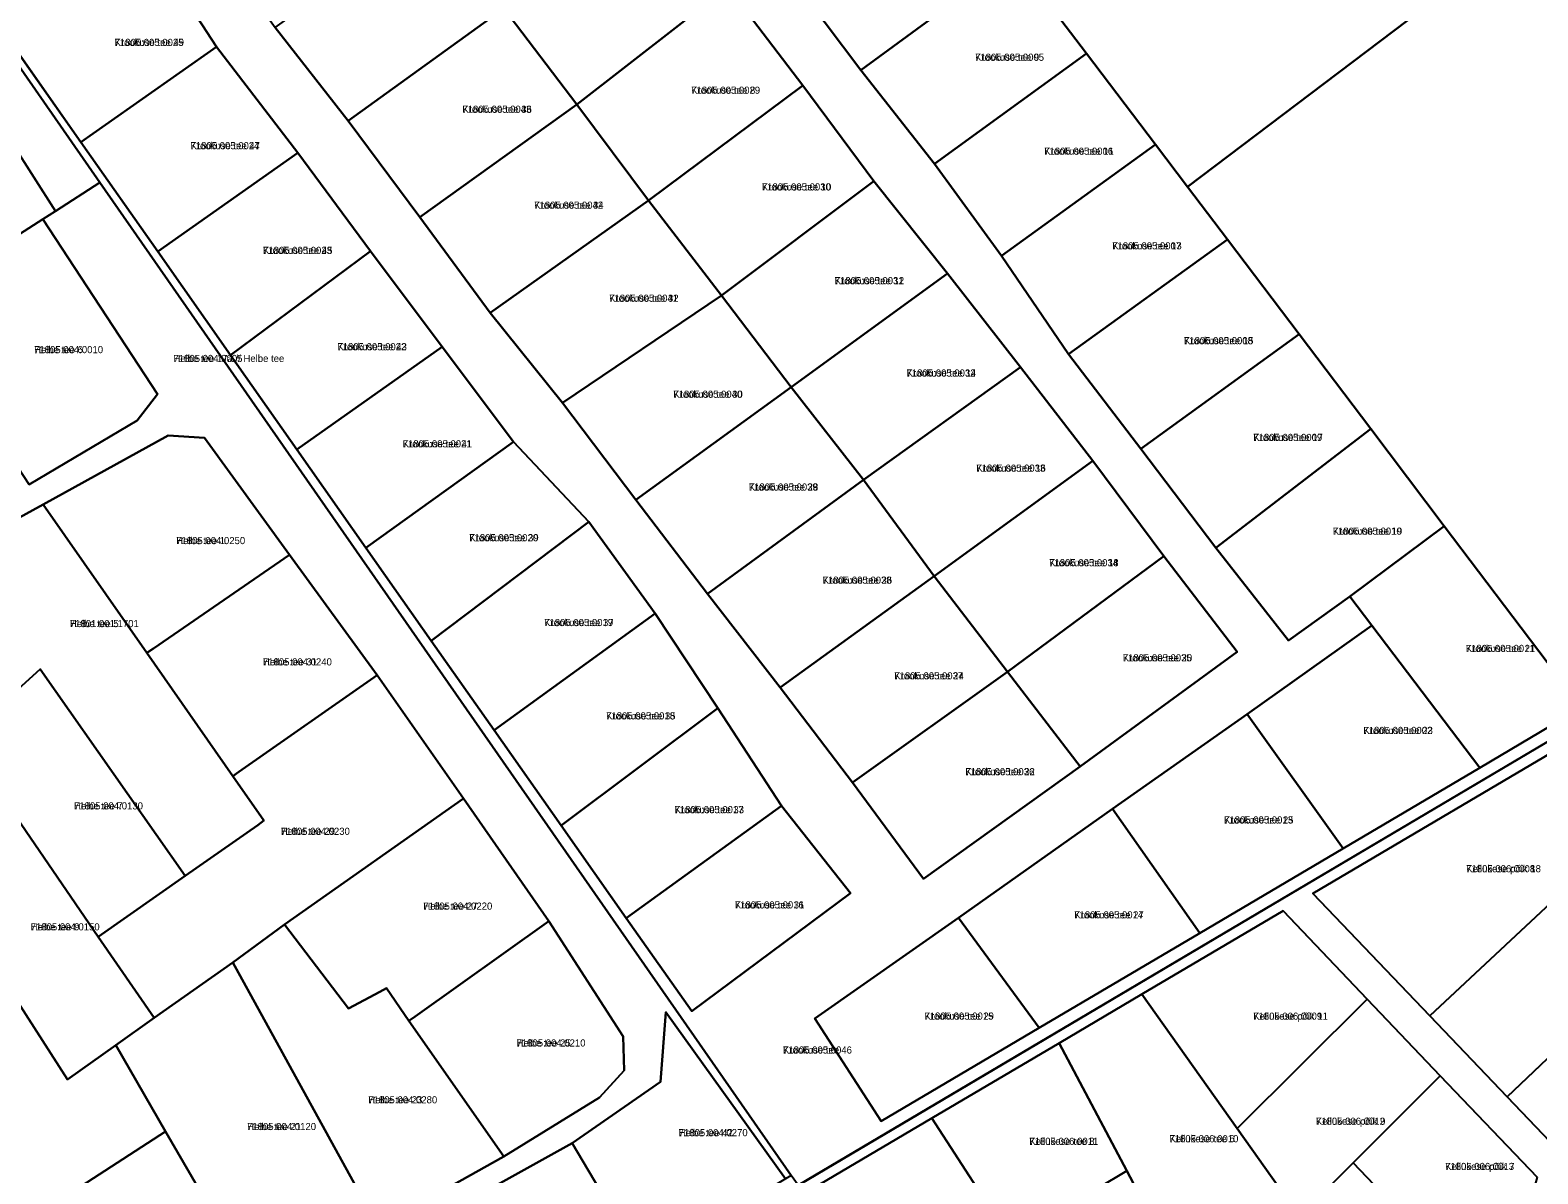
# Model space of a CAD drawing. Extents: x 529768 to 552006, y 6562269 to 6580975.
# Drawn here: x 537375.5 to 537692.6, y 6571376.5 to 6571616.9 of the extents above; entities that cross this region are included whole.
import ezdxf

# ---------------------------------------------------------------- set-up
doc = ezdxf.new("R2010")
doc.units = 0
for name, color, linetype in [('L_AADRESS', 7, 'Continuous'), ('PIIR', 7, 'Continuous'), ('TUNNUS', 7, 'Continuous')]:
    doc.layers.add(name, color=color, linetype=linetype)

msp = doc.modelspace()

# ---------------------------------------------------------------- linework, layer by layer
at = {"layer": 'PIIR'}
for points in [[(537705.45, 6571776.32), (537620.43, 6571720.13), (537608.13, 6571717.27), (537560.22, 6571727.03), (537538.31, 6571727.24), (537517.06, 6571718.48), (537405.45, 6571638.86), (537366.13, 6571621.92), (537364.81, 6571621.35), (537390.22, 6571584.9), (537380.85, 6571578.91), (537367.13, 6571600.3), (537358.41, 6571614.06), (537351.07, 6571620.07), (537333.77, 6571619.47), (537319.44, 6571621.89), (537293.18, 6571635.47), (537275.32, 6571646.66), (537274.57, 6571648.22), (537249.86, 6571668.81), (537225.83, 6571687.23), (537221.71, 6571690.16), (537199.69, 6571706.62)], [(537366.12, 6571621.91), (537386.19, 6571593.39), (537402.36, 6571570.39), (537417.68, 6571548.61), (537431.6, 6571528.81), (537446.16, 6571508.11), (537459.88, 6571488.59), (537473.14, 6571469.75), (537487.21, 6571449.73), (537500.9, 6571430.27), (537514.66, 6571410.7), (537548.06, 6571435.51), (537533.56, 6571453.9), (537520.13, 6571474.39), (537506.98, 6571494.34), (537493.05, 6571513.57), (537477.2, 6571530.4), (537462.2, 6571550.35), (537447.11, 6571570.5), (537431.84, 6571591.18), (537414.76, 6571613.42), (537401.45, 6571633.86)], [(537535.19, 6571628.52), (537550.19, 6571608.52), (537565.7, 6571588.83), (537579.79, 6571569.47), (537593.91, 6571548.8), (537609.07, 6571528.93), (537624.83, 6571508.14), (537640.15, 6571488.64), (537653.05, 6571497.89), (537657.65, 6571491.78), (537631.41, 6571473.17), (537603.1, 6571453.23), (537570.77, 6571430.31), (537540.57, 6571409.18), (537554.47, 6571387.56), (537587.72, 6571407.2), (537621.49, 6571427.14), (537651.63, 6571444.93), (537680.34, 6571461.88), (537701.77, 6571474.53)], [(537702.86, 6571472.26), (537537.01, 6571374.1), (537535.57, 6571376.16), (537390.22, 6571584.9), (537364.81, 6571621.35)], [(537375.33, 6571521.4), (537398.03, 6571534.85), (537402.31, 6571540.45), (537378.19, 6571577.21), (537380.85, 6571578.91), (537390.22, 6571584.9), (537535.57, 6571376.16), (537534.34, 6571375.44), (537509.23, 6571410.51), (537508.1, 6571395.88), (537489.48, 6571382.98), (537458.45, 6571365.69), (537427.46, 6571347.74), (537398.65, 6571330.25), (537369.5, 6571313.34)], [(537362.92, 6571428.14), (537383.38, 6571396.32), (537393.59, 6571403.57), (537404.02, 6571385.41), (537372.3, 6571364.86), (537394.07, 6571333.31), (537423.89, 6571351.18), (537448.72, 6571365.38), (537475.12, 6571380.13), (537495.26, 6571392.55), (537500.44, 6571398.27), (537500.24, 6571405.38), (537484.63, 6571429.61), (537466.68, 6571455.44), (537448.53, 6571481.33), (537430.06, 6571506.65), (537412.22, 6571531.24), (537404.55, 6571531.74), (537378.26, 6571517.21), (537372.52, 6571514.07)], [(537512.12, 6571217.83), (537499.61, 6571241.55), (537487.46, 6571264.58), (537473.18, 6571291.64), (537456.21, 6571323.81), (537430.08, 6571308.29), (537405.24, 6571293.53), (537380.07, 6571278.58), (537354.9, 6571263.63), (537324.81, 6571245.7), (537323.81, 6571247.48), (537484.12, 6571342.72), (537702.86, 6571472.26)], [(537703.91, 6571470.08), (537645.27, 6571435.48), (537669.84, 6571409.75), (537686.12, 6571392.7), (537701.15, 6571376.96)], [(537692.43, 6571375.8), (537672.05, 6571397.14), (537656.65, 6571413.26), (537638.98, 6571431.77), (537609.33, 6571414.28), (537591.93, 6571404.01), (537565.14, 6571388.2), (537538.79, 6571372.65)], [(537581.77, 6571362.6), (537606.13, 6571377.13), (537617.87, 6571354.91)]]:
    msp.add_lwpolyline(points, dxfattribs=at)
for points in [[(537517.06, 6571718.48), (537538.31, 6571727.24), (537560.22, 6571727.03), (537608.13, 6571717.27), (537620.43, 6571720.13), (537705.45, 6571776.32), (537748.76, 6571682.23), (537618.91, 6571583.97), (537612.15, 6571592.9), (537597.66, 6571612.03), (537582.41, 6571632.18), (537567.4, 6571652), (537552.32, 6571671.91), (537537.23, 6571691.84), (537521.77, 6571712.27)], [(537492.67, 6571665.14), (537477.72, 6571685.23), (537444.78, 6571661.16), (537412.49, 6571637.89), (537427.04, 6571617.51), (537442.39, 6571597.87), (537457.46, 6571577.65), (537472.27, 6571557.51), (537487.46, 6571538.57), (537502.9, 6571518.18), (537517.96, 6571498.43), (537533.26, 6571478.72), (537548.45, 6571458.79), (537563.38, 6571438.56), (537596.34, 6571462.13), (537629.32, 6571486.25), (537613.9, 6571506.35), (537599, 6571526.43), (537583.81, 6571546.1), (537568.44, 6571565.81), (537552.97, 6571585.17), (537537.99, 6571605.34), (537522.22, 6571626.04), (537507.54, 6571644.86)], [(537618.91, 6571583.97), (537748.76, 6571682.23), (537789.87, 6571620.04), (537820.56, 6571573.68), (537701.77, 6571474.53), (537672.9, 6571512.66), (537657.42, 6571533.1), (537642.35, 6571553.01), (537627.29, 6571572.91)], [(537582.41, 6571632.18), (537550.19, 6571608.52), (537535.19, 6571628.52), (537567.4, 6571652)], [(537522.22, 6571626.04), (537490.53, 6571601.29), (537475.18, 6571621.48), (537507.54, 6571644.86)], [(537475.18, 6571621.48), (537442.39, 6571597.87), (537427.04, 6571617.51), (537460.01, 6571641.01)], [(537414.76, 6571613.42), (537386.19, 6571593.39), (537366.13, 6571621.92), (537401.45, 6571633.86)], [(537597.66, 6571612.03), (537565.7, 6571588.83), (537550.19, 6571608.52), (537582.41, 6571632.18)], [(537537.99, 6571605.34), (537505.53, 6571581.1), (537490.53, 6571601.29), (537522.22, 6571626.04)], [(537490.53, 6571601.29), (537457.46, 6571577.65), (537442.39, 6571597.87), (537475.18, 6571621.48)], [(537431.84, 6571591.18), (537402.36, 6571570.39), (537386.19, 6571593.39), (537414.76, 6571613.42)], [(537612.15, 6571592.9), (537579.79, 6571569.47), (537565.7, 6571588.83), (537597.66, 6571612.03)], [(537552.97, 6571585.17), (537520.94, 6571561.14), (537505.53, 6571581.1), (537537.99, 6571605.34)], [(537505.53, 6571581.1), (537472.27, 6571557.51), (537457.46, 6571577.65), (537490.53, 6571601.29)], [(537380.85, 6571578.91), (537378.19, 6571577.21), (537350.44, 6571559.44), (537341.65, 6571553.81), (537327.15, 6571572.22), (537335.18, 6571578.46), (537367.13, 6571600.3)], [(537627.29, 6571572.91), (537593.91, 6571548.8), (537579.79, 6571569.47), (537612.15, 6571592.9), (537618.91, 6571583.97)], [(537447.11, 6571570.5), (537417.68, 6571548.61), (537402.36, 6571570.39), (537431.84, 6571591.18)], [(537568.44, 6571565.81), (537535.55, 6571541.88), (537520.94, 6571561.14), (537552.97, 6571585.17)], [(537520.94, 6571561.14), (537487.46, 6571538.57), (537472.27, 6571557.51), (537505.53, 6571581.1)], [(537350.44, 6571559.44), (537378.19, 6571577.21), (537402.31, 6571540.45), (537398.03, 6571534.85), (537375.33, 6571521.4)], [(537642.35, 6571553.01), (537609.07, 6571528.93), (537593.91, 6571548.8), (537627.29, 6571572.91)], [(537462.2, 6571550.35), (537431.6, 6571528.81), (537417.68, 6571548.61), (537447.11, 6571570.5)], [(537583.81, 6571546.1), (537550.77, 6571522.42), (537535.55, 6571541.88), (537568.44, 6571565.81)], [(537535.55, 6571541.88), (537502.9, 6571518.18), (537487.46, 6571538.57), (537520.94, 6571561.14)], [(537657.42, 6571533.1), (537624.83, 6571508.14), (537609.07, 6571528.93), (537642.35, 6571553.01)], [(537477.2, 6571530.4), (537446.16, 6571508.11), (537431.6, 6571528.81), (537462.2, 6571550.35)], [(537599, 6571526.43), (537565.65, 6571502.14), (537550.77, 6571522.42), (537583.81, 6571546.1)], [(537550.77, 6571522.42), (537517.96, 6571498.43), (537502.9, 6571518.18), (537535.55, 6571541.88)], [(537400.1, 6571486.04), (537378.26, 6571517.21), (537404.55, 6571531.74), (537412.22, 6571531.24), (537430.06, 6571506.65), (537401.46, 6571486.95)], [(537672.9, 6571512.66), (537653.05, 6571497.89), (537640.15, 6571488.64), (537624.83, 6571508.14), (537657.42, 6571533.1)], [(537493.05, 6571513.57), (537459.88, 6571488.59), (537446.16, 6571508.11), (537477.2, 6571530.4)], [(537613.9, 6571506.35), (537581.04, 6571482.06), (537565.65, 6571502.14), (537599, 6571526.43)], [(537565.65, 6571502.14), (537533.26, 6571478.72), (537517.96, 6571498.43), (537550.77, 6571522.42)], [(537372.52, 6571514.07), (537378.26, 6571517.21), (537400.1, 6571486.04), (537418.16, 6571460.13), (537424.7, 6571450.77), (537423.42, 6571449.83), (537408.17, 6571439.14), (537377.62, 6571482.62), (537361.36, 6571467.9), (537343.08, 6571493.7)], [(537506.98, 6571494.34), (537473.14, 6571469.75), (537459.88, 6571488.59), (537493.05, 6571513.57)], [(537701.77, 6571474.53), (537680.34, 6571461.88), (537657.65, 6571491.78), (537653.05, 6571497.89), (537672.9, 6571512.66)], [(537418.16, 6571460.13), (537400.1, 6571486.04), (537401.46, 6571486.95), (537430.06, 6571506.65), (537448.53, 6571481.33), (537419.46, 6571461.04)], [(537629.32, 6571486.25), (537596.34, 6571462.13), (537581.04, 6571482.06), (537613.9, 6571506.35)], [(537581.04, 6571482.06), (537548.45, 6571458.79), (537533.26, 6571478.72), (537565.65, 6571502.14)], [(537520.13, 6571474.39), (537487.21, 6571449.73), (537473.14, 6571469.75), (537506.98, 6571494.34)], [(537680.34, 6571461.88), (537651.63, 6571444.93), (537631.41, 6571473.17), (537657.65, 6571491.78)], [(537361.36, 6571467.9), (537377.62, 6571482.62), (537408.17, 6571439.14), (537389.86, 6571426.36), (537366.01, 6571461.12)], [(537418.16, 6571420.97), (537401.64, 6571409.33), (537389.86, 6571426.36), (537408.17, 6571439.14), (537423.42, 6571449.83), (537424.7, 6571450.77), (537418.16, 6571460.13), (537419.46, 6571461.04), (537448.53, 6571481.33), (537466.68, 6571455.44), (537429.05, 6571428.91)], [(537596.34, 6571462.13), (537563.38, 6571438.56), (537548.45, 6571458.79), (537581.04, 6571482.06)], [(537533.56, 6571453.9), (537500.9, 6571430.27), (537487.21, 6571449.73), (537520.13, 6571474.39)], [(537651.63, 6571444.93), (537621.49, 6571427.14), (537603.1, 6571453.23), (537631.41, 6571473.17)], [(537669.84, 6571409.75), (537645.27, 6571435.48), (537703.91, 6571470.08), (537717.58, 6571454.27)], [(537383.38, 6571396.32), (537362.92, 6571428.14), (537349.68, 6571448.52), (537366.01, 6571461.12), (537389.86, 6571426.36), (537401.64, 6571409.33), (537393.59, 6571403.57)], [(537449.05, 6571414.78), (537442.51, 6571411.27), (537429.05, 6571428.91), (537466.68, 6571455.44), (537484.63, 6571429.61), (537456.53, 6571409.58), (537455.2, 6571408.66), (537450.48, 6571415.52)], [(537548.06, 6571435.51), (537514.66, 6571410.7), (537500.9, 6571430.27), (537533.56, 6571453.9)], [(537603.1, 6571453.23), (537621.49, 6571427.14), (537587.72, 6571407.2), (537570.77, 6571430.31)], [(537686.12, 6571392.7), (537669.84, 6571409.75), (537717.58, 6571454.27), (537732.61, 6571436.86)], [(537701.15, 6571376.96), (537686.12, 6571392.7), (537732.61, 6571436.86), (537750.66, 6571415.98), (537713.75, 6571383.85)], [(537587.72, 6571407.2), (537554.47, 6571387.56), (537540.57, 6571409.18), (537570.77, 6571430.31)], [(537656.65, 6571413.26), (537629.35, 6571386.06), (537609.33, 6571414.28), (537638.98, 6571431.77)], [(537429.05, 6571428.91), (537442.51, 6571411.27), (537449.05, 6571414.78), (537450.48, 6571415.52), (537455.2, 6571408.66), (537475.12, 6571380.13), (537448.72, 6571365.38), (537418.16, 6571420.97)], [(537455.2, 6571408.66), (537456.53, 6571409.58), (537484.63, 6571429.61), (537500.24, 6571405.38), (537500.44, 6571398.27), (537495.26, 6571392.55), (537475.12, 6571380.13)], [(537404.02, 6571385.41), (537393.59, 6571403.57), (537401.64, 6571409.33), (537418.16, 6571420.97), (537448.72, 6571365.38), (537423.89, 6571351.18)], [(537638.27, 6571373.5), (537623.86, 6571360.37), (537617.87, 6571354.91), (537606.13, 6571377.13), (537591.93, 6571404.01), (537609.33, 6571414.28), (537629.35, 6571386.06)], [(537672.05, 6571397.14), (537653.72, 6571378.82), (537642.37, 6571367.41), (537629.8, 6571362.63), (537623.86, 6571360.37), (537638.27, 6571373.5), (537629.35, 6571386.06), (537656.65, 6571413.26)], [(537489.48, 6571382.98), (537508.1, 6571395.88), (537509.23, 6571410.51), (537534.34, 6571375.44), (537504.53, 6571357.68)], [(537606.13, 6571377.13), (537581.77, 6571362.6), (537565.14, 6571388.2), (537591.93, 6571404.01)], [(537692.43, 6571375.8), (537691.33, 6571371.87), (537675.56, 6571355.97), (537653.72, 6571378.82), (537672.05, 6571397.14)], [(537554.85, 6571346.55), (537538.79, 6571372.65), (537565.14, 6571388.2), (537581.77, 6571362.6)], [(537423.89, 6571351.18), (537394.07, 6571333.31), (537372.3, 6571364.86), (537404.02, 6571385.41)], [(537458.45, 6571365.69), (537489.48, 6571382.98), (537504.53, 6571357.68), (537474.31, 6571339.66)], [(537655.91, 6571336.16), (537629.8, 6571362.63), (537642.37, 6571367.41), (537653.72, 6571378.82), (537675.56, 6571355.97)]]:
    msp.add_lwpolyline(points, close=True, dxfattribs=at)

# ---------------------------------------------------------------- texts
at = {"layer": 'L_AADRESS'}
for s, p in [('Krookuse tee 49', (537393.29, 6571613.62)), ('Krookuse tee 9', (537574.23, 6571610.5)), ('Krookuse tee 8', (537514.53, 6571603.57)), ('Krookuse tee 36', (537466.43, 6571599.57)), ('Krookuse tee 47', (537409.26, 6571591.91)), ('Krookuse tee 11', (537588.76, 6571590.75)), ('Krookuse tee 10', (537529.4, 6571583.24)), ('Krookuse tee 34', (537481.52, 6571579.4)), ('Krookuse tee 45', (537424.5, 6571569.9)), ('Krookuse tee 13', (537603.07, 6571570.85)), ('Krookuse tee 12', (537544.71, 6571563.53)), ('Krookuse tee 32', (537497.28, 6571559.84)), ('Helbe tee 6', (537376.38, 6571549.03)), ('Krookuse tee 43', (537440.15, 6571549.65)), ('Krookuse tee 15', (537618.15, 6571550.92)), ('Helbe tee 17a // Helbe tee', (537405.68, 6571547.18)), ('Krookuse tee 14', (537559.83, 6571544.12)), ('Krookuse tee 30', (537510.78, 6571539.66)), ('Krookuse tee 17', (537632.73, 6571530.58)), ('Krookuse tee 41', (537453.88, 6571529.23)), ('Krookuse tee 16', (537574.49, 6571524.12)), ('Krookuse tee 28', (537526.65, 6571520.15)), ('Krookuse tee 19', (537649.44, 6571510.87)), ('Helbe tee 1', (537406.26, 6571508.89)), ('Krookuse tee 39', (537467.86, 6571509.49)), ('Krookuse tee 18', (537589.8, 6571504.24)), ('Krookuse tee 26', (537542.18, 6571500.57)), ('Helbe tee 5', (537383.89, 6571491.44)), ('Krookuse tee 37', (537483.62, 6571491.66)), ('Krookuse tee 21', (537677.41, 6571486.22)), ('Helbe tee 31', (537424.49, 6571483.39)), ('Krookuse tee 20', (537605.28, 6571484.24)), ('Krookuse tee 24', (537557.24, 6571480.46)), ('Krookuse tee 35', (537496.64, 6571472.04)), ('Krookuse tee 23', (537655.88, 6571468.98)), ('Krookuse tee 22', (537572.19, 6571460.31)), ('Helbe tee 7', (537384.77, 6571453.12)), ('Krookuse tee 33', (537511.04, 6571452.33)), ('Helbe tee 29', (537428.27, 6571447.77)), ('Krookuse tee 25', (537626.58, 6571450.16)), ('Kellukese põik 18', (537677.49, 6571439.91)), ('Helbe tee 27', (537458.22, 6571432.05)), ('Krookuse tee 31', (537523.72, 6571432.3)), ('Krookuse tee 27', (537595.08, 6571430.21)), ('Helbe tee 9', (537375.66, 6571427.69)), ('Krookuse tee 29', (537563.59, 6571408.93)), ('Kellukese põik 11', (537632.71, 6571408.91)), ('Helbe tee 25', (537477.82, 6571403.28)), ('Krookuse tee', (537533.84, 6571401.8)), ('Helbe tee 23', (537446.64, 6571391.33)), ('Helbe tee 21', (537421.16, 6571385.71)), ('Helbe tee 42', (537511.91, 6571384.42)), ('Kellukese põik 9', (537645.91, 6571386.82)), ('Kellukese tee 8', (537585.64, 6571382.6)), ('Kellukese tee 6', (537615.1, 6571383.15)), ('Kellukese põik 7', (537673.07, 6571377.32))]:
    msp.add_text(s, height=1.5, dxfattribs=at).set_placement(p)
at = {"layer": 'TUNNUS'}
for s, p in [('71805:005:0025', (537393.29, 6571613.62)), ('71805:005:0005', (537574.23, 6571610.5)), ('71805:005:0029', (537514.53, 6571603.57)), ('71805:005:0043', (537466.43, 6571599.57)), ('71805:005:0024', (537409.26, 6571591.91)), ('71805:005:0006', (537588.76, 6571590.75)), ('71805:005:0030', (537529.4, 6571583.24)), ('71805:005:0042', (537481.52, 6571579.4)), ('71805:005:0023', (537424.5, 6571569.9)), ('71805:005:0007', (537603.07, 6571570.85)), ('71805:005:0031', (537544.71, 6571563.53)), ('71805:005:0041', (537497.28, 6571559.84)), ('71805:004:0010', (537376.38, 6571549.03)), ('71805:005:0022', (537440.15, 6571549.65)), ('71805:005:0008', (537618.15, 6571550.92)), ('71805:004:0005', (537405.68, 6571547.18)), ('71805:005:0032', (537559.83, 6571544.12)), ('71805:005:0040', (537510.78, 6571539.66)), ('71805:005:0009', (537632.73, 6571530.58)), ('71805:005:0021', (537453.88, 6571529.23)), ('71805:005:0033', (537574.49, 6571524.12)), ('71805:005:0039', (537526.65, 6571520.15)), ('71805:004:0250', (537406.26, 6571508.89)), ('71805:005:0020', (537467.86, 6571509.49)), ('71805:005:0010', (537649.44, 6571510.87)), ('71805:005:0034', (537589.8, 6571504.24)), ('71805:005:0038', (537542.18, 6571500.57)), ('71801:001:1701', (537383.89, 6571491.44)), ('71805:005:0019', (537483.62, 6571491.66)), ('71805:005:0011', (537677.41, 6571486.22)), ('71805:004:0240', (537424.49, 6571483.39)), ('71805:005:0035', (537605.28, 6571484.24)), ('71805:005:0037', (537557.24, 6571480.46)), ('71805:005:0018', (537496.64, 6571472.04)), ('71805:005:0002', (537655.88, 6571468.98)), ('71805:005:0036', (537572.19, 6571460.31)), ('71805:004:0130', (537384.77, 6571453.12)), ('71805:005:0017', (537511.04, 6571452.33)), ('71805:004:0230', (537428.27, 6571447.77)), ('71805:005:0013', (537626.58, 6571450.16)), ('71805:006:0008', (537677.49, 6571439.91)), ('71805:004:0220', (537458.22, 6571432.05)), ('71805:005:0016', (537523.72, 6571432.3)), ('71805:005:0014', (537595.08, 6571430.21)), ('71805:004:0150', (537375.66, 6571427.69)), ('71805:005:0015', (537563.59, 6571408.93)), ('71805:006:0009', (537632.71, 6571408.91)), ('71805:004:0210', (537477.82, 6571403.28)), ('71805:005:0046', (537533.84, 6571401.8)), ('71805:004:0280', (537446.64, 6571391.33)), ('71805:004:0120', (537421.16, 6571385.71)), ('71805:004:0270', (537511.91, 6571384.42)), ('71805:006:0012', (537645.91, 6571386.82)), ('71805:006:0011', (537585.64, 6571382.6)), ('71805:006:0010', (537615.1, 6571383.15)), ('71805:006:0013', (537673.07, 6571377.32))]:
    msp.add_text(s, height=1.5, dxfattribs=at).set_placement(p)

doc.saveas('drawing.dxf')
